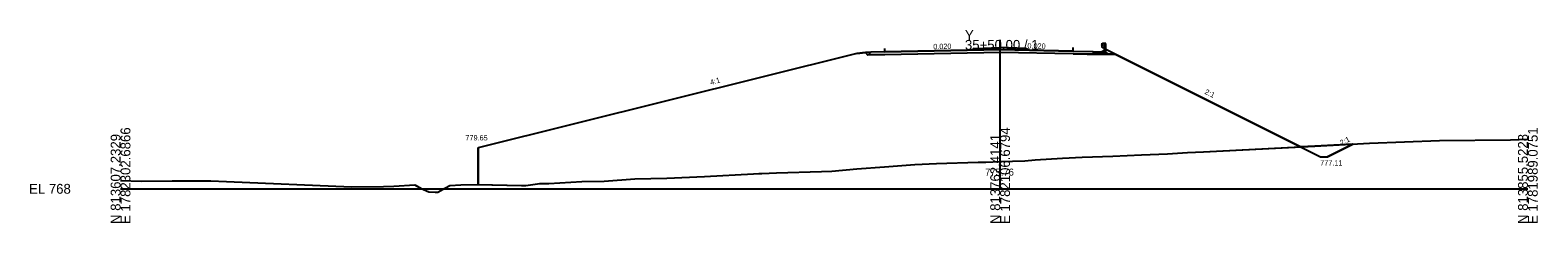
# Model space of a CAD drawing. Extents: x -12583 to 5303, y -44 to 25667.
# Drawn here: x 1874.3 to 2302.8, y 5990.3 to 6045.2 of the extents above; entities that cross this region are included whole.
import ezdxf

# ---------------------------------------------------------------- set-up
doc = ezdxf.new("R2010")
doc.units = 0
for name, color, linetype in [('Exist Cross Section Cell', 7, 'Continuous'), ('Exist XS Center Line Elevation Label', 7, 'Continuous'), ('Exist XS Ground Line', 7, 'Continuous'), ('Prop Conc 5in Monolithic Surface Mount Island', 7, 'Continuous'), ('Prop XS Ditch Standard Text', 7, 'Continuous'), ('Prop XS Dump Level', 7, 'Continuous'), ('Prop XS Earthwork Shape', 7, 'Continuous'), ('Prop XS EOT Tick Mark', 7, 'Continuous'), ('Prop XS Finish Grade', 7, 'Continuous'), ('Prop XS Finish Grade CurbGutter', 7, 'Continuous'), ('Prop XS Finish Grade Earthwork', 7, 'Continuous'), ('Prop XS Finish Grade Paved Shoulder', 7, 'Continuous'), ('Prop XS Finish Grade Pavement', 7, 'Continuous'), ('Prop XS Guardrail', 7, 'Continuous'), ('Prop XS Pvmt Edge Slope', 7, 'Continuous'), ('Prop XS SE Text', 7, 'Continuous'), ('Prop XS Side Slope Text', 7, 'Continuous'), ('Prop XS Subgrade CurbGutter', 7, 'Continuous'), ('Prop XS Subgrade Earthwork', 7, 'Continuous')]:
    doc.layers.add(name, color=color, linetype=linetype)

msp = doc.modelspace()

# ---------------------------------------------------------------- linework, layer by layer
at = {"layer": 'Exist Cross Section Cell'}
for p, q in [((2150, 6000), (2150, 6042.36)), ((1900, 6000), (2150, 6000)), ((2150, 6000), (2300, 6000))]:
    msp.add_line(p, q, dxfattribs=at)
at = {"layer": 'Exist XS Ground Line'}
for p, q in [((2239.49, 6012.12), (2254.99, 6012.96)), ((2254.99, 6012.96), (2274.85, 6013.72)), ((2274.85, 6013.72), (2295.08, 6013.95)), ((2295.08, 6013.95), (2300, 6014.12)), ((2157.02, 6008), (2159.95, 6008.24)), ((2159.95, 6008.24), (2167.77, 6008.71)), ((2167.77, 6008.71), (2173.36, 6008.98)), ((2173.36, 6008.98), (2182.08, 6009.31)), ((2182.08, 6009.31), (2190.2, 6009.63)), ((2190.2, 6009.63), (2197.57, 6009.98)), ((2197.57, 6009.98), (2203.3, 6010.38)), ((2203.3, 6010.38), (2207.81, 6010.54)), ((2207.81, 6010.54), (2239.49, 6012.12)), ((2065.96, 6003.46), (2079.86, 6004.3)), ((2079.86, 6004.3), (2081.42, 6004.39)), ((2081.42, 6004.39), (2082.32, 6004.4)), ((2082.32, 6004.4), (2086.41, 6004.54)), ((2086.41, 6004.54), (2099.2, 6004.96)), ((2099.2, 6004.96), (2102.14, 6005.03)), ((2102.14, 6005.03), (2109.28, 6005.71)), ((2109.28, 6005.71), (2117.15, 6006.27)), ((2117.15, 6006.27), (2125.79, 6006.93)), ((2125.79, 6006.93), (2131.91, 6007.24)), ((2131.91, 6007.24), (2143.76, 6007.55)), ((2143.76, 6007.55), (2145.92, 6007.63)), ((2145.92, 6007.63), (2150, 6007.76)), ((2150, 6007.76), (2157.02, 6008)), ((1900, 6002.37), (1905.98, 6002.17)), ((1905.98, 6002.17), (1914.67, 6002.25)), ((1914.67, 6002.25), (1923.08, 6002.23)), ((1923.08, 6002.23), (1925.63, 6002.25)), ((1925.63, 6002.25), (1930.13, 6002.09)), ((1930.13, 6002.09), (1965.64, 6000.6)), ((1965.64, 6000.6), (1974.7, 6000.67)), ((1974.7, 6000.67), (1977.67, 6000.8)), ((1977.67, 6000.8), (1983.6, 6001.17)), ((1983.6, 6001.17), (1985.49, 6000.12)), ((1985.49, 6000.12), (1987.67, 5999.1)), ((1990.14, 5999.06), (1992.38, 6000.25)), ((1992.38, 6000.25), (1993.64, 6000.98)), ((1993.64, 6000.98), (1996.69, 6001.12)), ((1996.69, 6001.12), (2001.38, 6001.22)), ((2001.38, 6001.22), (2014.01, 6000.95)), ((2014.01, 6000.95), (2015.23, 6000.97)), ((2015.23, 6000.97), (2019.22, 6001.49)), ((2019.22, 6001.49), (2021.77, 6001.54)), ((2021.77, 6001.54), (2031.08, 6002.06)), ((2031.08, 6002.06), (2037.5, 6002.2)), ((2037.5, 6002.2), (2046.22, 6002.81)), ((2046.22, 6002.81), (2055.27, 6003.07)), ((2055.27, 6003.07), (2065.96, 6003.46)), ((1987.67, 5999.1), (1989.38, 5999.07)), ((1989.38, 5999.07), (1990.14, 5999.06))]:
    msp.add_line(p, q, dxfattribs=at)
at = {"layer": 'Prop Conc 5in Monolithic Surface Mount Island'}
for p, q in [((2142, 6039.61), (2142.74, 6039.88)), ((2142, 6039.45), (2142, 6039.61)), ((2142.74, 6039.88), (2150, 6040.17)), ((2157.26, 6039.88), (2150, 6040.17)), ((2158, 6039.61), (2157.26, 6039.88)), ((2158, 6039.45), (2158, 6039.61))]:
    msp.add_line(p, q, dxfattribs=at)
at = {"layer": 'Prop XS Dump Level'}
for p, q in [((2150, 6039.61), (2117.25, 6038.95)), ((2170.75, 6039.19), (2150, 6039.61))]:
    msp.add_line(p, q, dxfattribs=at)
at = {"layer": 'Prop XS Earthwork Shape'}
for points in [[(2046.22, 6002.81), (2055.27, 6003.07), (2065.96, 6003.46), (2079.86, 6004.3), (2081.42, 6004.39), (2082.32, 6004.4), (2086.41, 6004.54), (2099.2, 6004.96), (2102.14, 6005.03), (2109.28, 6005.71), (2117.15, 6006.27), (2125.79, 6006.93), (2131.91, 6007.24), (2143.76, 6007.55), (2145.92, 6007.63), (2150, 6007.76), (2157.02, 6008), (2159.95, 6008.24), (2167.77, 6008.71), (2173.36, 6008.98), (2182.08, 6009.31), (2190.2, 6009.63), (2197.57, 6009.98), (2203.3, 6010.38), (2207.81, 6010.54), (2235.41, 6011.92), (2182.68, 6038.28), (2180.81, 6038.28), (2176.42, 6038.29), (2174.75, 6038.32), (2170.75, 6038.4), (2150, 6038.82), (2117.25, 6038.16), (2113.25, 6038.08), (2112.44, 6038.06), (2111.75, 6038.75), (2109.25, 6038.55), (2001.65, 6011.65), (2001.65, 6001.21), (2014.01, 6000.95), (2015.23, 6000.97), (2019.22, 6001.49), (2021.77, 6001.54), (2031.08, 6002.06), (2037.5, 6002.2)], [(2241.03, 6009.11), (2243.03, 6009.11), (2250.21, 6012.7), (2239.49, 6012.12), (2235.41, 6011.92)]]:
    msp.add_lwpolyline(points, close=True, dxfattribs=at)
at = {"layer": 'Prop XS EOT Tick Mark'}
for p, q in [((2117.25, 6038.95), (2117.25, 6039.95)), ((2170.75, 6039.19), (2170.75, 6040.19))]:
    msp.add_line(p, q, dxfattribs=at)
at = {"layer": 'Prop XS Finish Grade'}
for p, q in [((2113.25, 6038.87), (2111.75, 6038.75)), ((2179.44, 6039.33), (2180.02, 6039.62)), ((2182.68, 6038.28), (2180.02, 6039.62))]:
    msp.add_line(p, q, dxfattribs=at)
at = {"layer": 'Prop XS Finish Grade CurbGutter'}
for p, q in [((2176.42, 6039.08), (2178.75, 6038.99)), ((2178.75, 6038.99), (2179.44, 6039.33))]:
    msp.add_line(p, q, dxfattribs=at)
at = {"layer": 'Prop XS Finish Grade Earthwork'}
for p, q in [((2109.25, 6038.55), (2001.65, 6011.65)), ((2109.25, 6038.55), (2111.75, 6038.75)), ((2182.68, 6038.28), (2241.03, 6009.11)), ((2250.21, 6012.7), (2243.03, 6009.11)), ((2001.65, 6001.21), (2001.65, 6011.65)), ((2241.03, 6009.11), (2243.03, 6009.11))]:
    msp.add_line(p, q, dxfattribs=at)
at = {"layer": 'Prop XS Finish Grade Paved Shoulder'}
for p, q in [((2117.25, 6038.95), (2113.25, 6038.87)), ((2170.75, 6039.19), (2176.42, 6039.08))]:
    msp.add_line(p, q, dxfattribs=at)
at = {"layer": 'Prop XS Finish Grade Pavement'}
for p, q in [((2117.25, 6038.95), (2150, 6039.61)), ((2150, 6039.61), (2170.75, 6039.19))]:
    msp.add_line(p, q, dxfattribs=at)
at = {"layer": 'Prop XS Guardrail'}
for p, q in [((2178.78, 6041.18), (2178.75, 6041.12)), ((2178.75, 6041.12), (2178.78, 6041.06)), ((2178.78, 6040.57), (2178.75, 6040.51)), ((2178.75, 6040.51), (2178.78, 6040.45)), ((2179.07, 6041.38), (2178.78, 6041.18)), ((2178.78, 6041.06), (2179.07, 6040.86)), ((2179.07, 6040.77), (2178.78, 6040.57)), ((2178.78, 6040.45), (2179.07, 6040.25)), ((2179.57, 6041.38), (2179.07, 6041.38)), ((2179.07, 6040.86), (2179.07, 6040.77)), ((2179.07, 6040.25), (2179.57, 6040.25)), ((2180.07, 6041.38), (2179.57, 6041.38)), ((2179.57, 6041.38), (2179.57, 6038.88)), ((2180.07, 6038.88), (2180.07, 6041.38))]:
    msp.add_line(p, q, dxfattribs=at)
at = {"layer": 'Prop XS Pvmt Edge Slope'}
for p, q in [((2113.25, 6038.87), (2112.44, 6038.06)), ((2179.44, 6038.66), (2180.44, 6038.66)), ((2180.44, 6038.66), (2180.81, 6038.28))]:
    msp.add_line(p, q, dxfattribs=at)
at = {"layer": 'Prop XS Subgrade CurbGutter'}
for p, q in [((2176.42, 6039.08), (2176.42, 6038.66)), ((2176.42, 6038.66), (2179.44, 6038.66)), ((2179.44, 6038.66), (2179.44, 6039.33))]:
    msp.add_line(p, q, dxfattribs=at)
at = {"layer": 'Prop XS Subgrade Earthwork'}
for p, q in [((2112.44, 6038.06), (2111.75, 6038.75)), ((2113.25, 6038.08), (2112.44, 6038.06)), ((2117.25, 6038.16), (2113.25, 6038.08)), ((2150, 6038.82), (2117.25, 6038.16)), ((2170.75, 6038.4), (2150, 6038.82)), ((2170.75, 6038.4), (2174.75, 6038.32)), ((2174.75, 6038.32), (2176.42, 6038.29)), ((2176.42, 6038.29), (2176.42, 6038.28)), ((2176.42, 6038.28), (2180.81, 6038.28)), ((2180.81, 6038.28), (2182.68, 6038.28))]:
    msp.add_line(p, q, dxfattribs=at)

# ---------------------------------------------------------------- texts
at = {"layer": 'Exist Cross Section Cell'}
for s, p in [('Y', (2140, 6042.36)), ('35+50.00 / 1', (2140, 6039.56)), ('EL 768', (1874, 5998.6))]:
    msp.add_text(s, height=2.8, dxfattribs=at).set_placement(p)
for s, p in [('E 1782302.6866', (1902.8, 5990)), ('E 1782106.6794', (2152.8, 5990)), ('E 1781989.0751', (2302.8, 5990)), ('N 813607.2329', (1900, 5990)), ('N 813762.4141', (2150, 5990)), ('N 813855.5228', (2300, 5990))]:
    msp.add_text(s, height=2.8, rotation=90, dxfattribs=at).set_placement(p)
at = {"layer": 'Exist XS Center Line Elevation Label'}
msp.add_text('775.76', height=2, dxfattribs=at).set_placement((2145.73, 6003.76))
at = {"layer": 'Prop XS Ditch Standard Text'}
for s, p in [('779.65', (1998.02, 6013.77)), ('777.11', (2240.97, 6006.63))]:
    msp.add_text(s, height=1.5, dxfattribs=at).set_placement(p)
at = {"layer": 'Prop XS Dump Level'}
for p in [(2109.25, 6038.51), (2176.42, 6039.04)]:
    msp.add_text('Case2', height=0.04, dxfattribs=at).set_placement(p)
at = {"layer": 'Prop XS SE Text'}
for rotation, p in [(1.1458, (2131, 6039.73)), (358.8542, (2157.75, 6039.95))]:
    msp.add_text('0.020', height=1.5, rotation=rotation, dxfattribs=at).set_placement(p)
at = {"layer": 'Prop XS Side Slope Text'}
for s, rotation, p in [('4:1', 15.8195, (2067.8, 6029.52)), ('2:1', 333.4349, (2207.99, 6027.11)), ('2:1', 26.5651, (2247.03, 6012.31))]:
    msp.add_text(s, height=1.5, rotation=rotation, dxfattribs=at).set_placement(p)

doc.saveas('drawing.dxf')
